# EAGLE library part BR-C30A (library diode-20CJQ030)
Blue Radio's BR-C30 Class1, Class2, and Class3 Bluetooth® ver1.2 OUTLINE: AT HOME. AT WORK. ON THE ROAD. USING BLUETOOTH WIRELESS TECHNOLOGY MEANS TOTAL FREEDOM FROM THE CONSTRAINTS AND CLUTTER OF WIRES IN YOUR LIFE. Wireless communications module certified to Bluetooth® v1.2. Two types of models: With/without ceramic RF chip antenna provided. FCC, CE, Industry Canada, RoHS, and Bluetooth® certified ISM 2.4GHz band module. UART data, and PCM audio interfaces available to various applications. Includes integrated software stack, profiles, and AT modem like commands. Embedded Bluetooth Stack Profiles Included (requires no host MCU stack): SPP, DUN, LAN, PAN, Headset, Audio Gateway, FTP, GAP SDP, RFCOMM, and L2CAP protocols. FEATURES: The BlueRadios serial radio modems can be configured, commanded, and controlled through simple ASCII strings over the Bluetooth RF link or directly through the hardware serial UART. Dedicated PCM voice channel for audio applications UART baud rate speeds: 1200bps up to 921.6Kbps, and customized +100 meter (330 feet) distance Software adjustable transmitter power from short to long range applications Low power consumption (120mA TX, 40mA RX, 2mA idle mode, and 90uA deep sleep) Small-form factor SMT radio modem Self-discovery and network equipped multi-points Operating temperature range: -40~+70ºC. Secure and robust communication link - FHSS (Frequency Hopping Spread Spectrum) - Encryption and 16 alphanumeric Personal Identification Number (PIN) -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
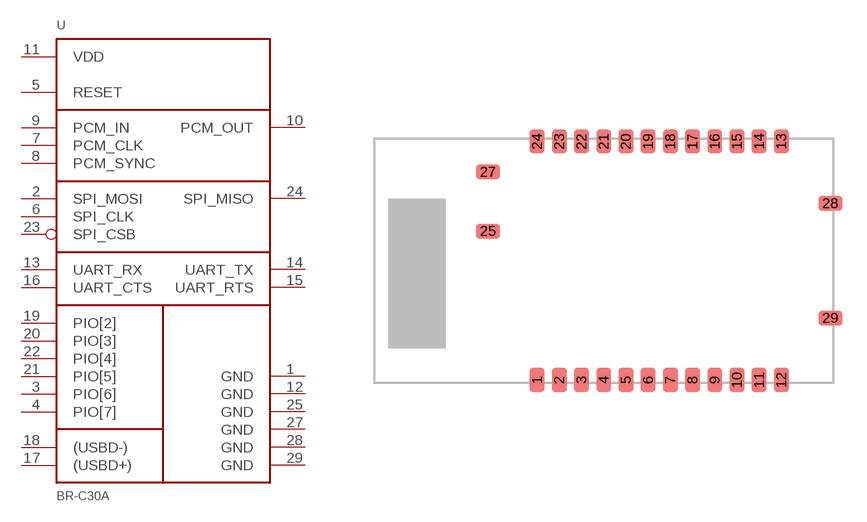
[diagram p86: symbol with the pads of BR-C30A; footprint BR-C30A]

Designator prefix U

## BR-C30A  [BR-C30A]
1  GND  pwr
2  SPI_MOSI  in
3  PIO[6]
4  PIO[7]
5  RESET  in
6  SPI_CLK  in
7  PCM_CLK
8  PCM_SYNC
9  PCM_IN  in
10  PCM_OUT  out
11  VDD  pwr
12  GND  pwr
13  UART_RX  in
14  UART_TX  out
15  UART_RTS  out
16  UART_CTS  in
17  (USBD+)
18  (USBD-)
19  PIO[2]
20  PIO[3]
21  PIO[5]
22  PIO[4]
23  SPI_CSB  in
24  SPI_MISO  out
25  GND  pwr
27  GND  pwr
28  GND  pwr
29  GND  pwr

## Footprint BR-C30A (pad centres in mm)
smd 0.8 x 1.3: 1 -3.6,-6.45; 2 -2.4,-6.45; 3 -1.2,-6.45; 4 0,-6.45; 5 1.2,-6.45; 6 2.4,-6.45; 7 3.6,-6.45; 8 4.8,-6.45; 9 6,-6.45; 10 7.2,-6.45; 11 8.4,-6.45; 12 9.6,-6.45; 13 9.6,6.45; 14 8.4,6.45; 15 7.2,6.45; 16 6,6.45; 17 4.8,6.45; 18 3.6,6.45; 19 2.4,6.45; 20 1.2,6.45; 21 0,6.45; 22 -1.2,6.45; 23 -2.4,6.45; 24 -3.6,6.45
smd 1.3 x 0.8: 25 -6.25,1.6; 27 -6.25,4.8; 28 12.25,3.1; 29 12.25,-3.1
